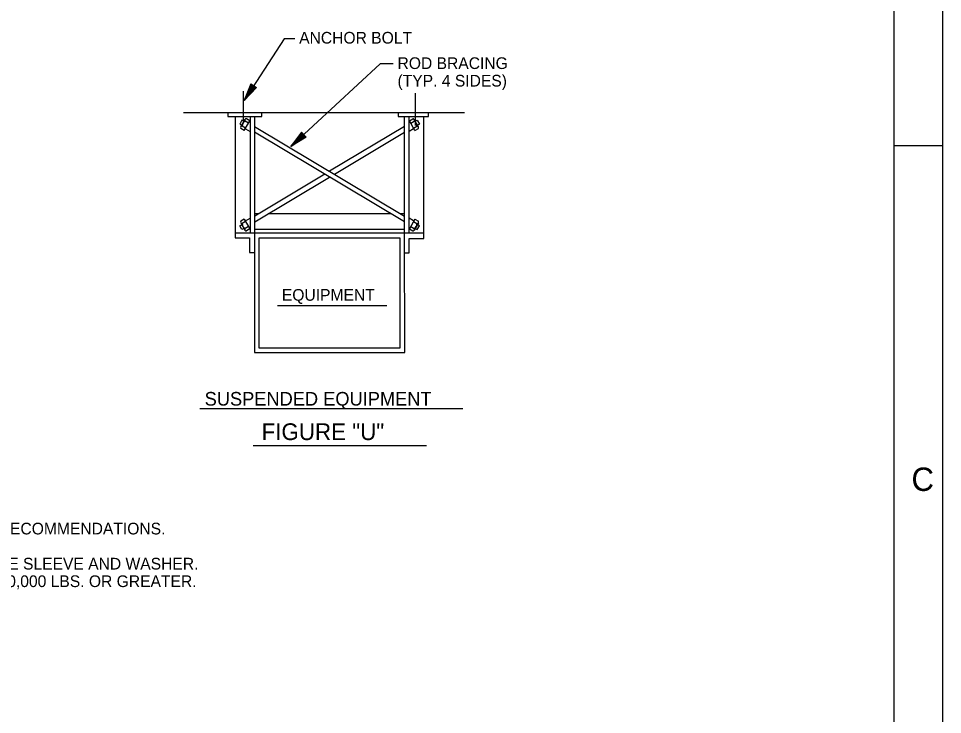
# Model space of a CAD drawing. Extents: x 9999.96 to 10005.26, y 9999.88 to 10002.38.
# Drawn here: x 10002.67 to 10003.46, y 10001.252 to 10001.847 of the extents above; entities that cross this region are included whole.
import ezdxf

# ---------------------------------------------------------------- set-up
doc = ezdxf.new("R2010")
doc.units = 0
doc.layers.add('Level 1', color=7, linetype='Continuous')
doc.layers.add('Level 2', color=7, linetype='Continuous')

msp = doc.modelspace()

# ---------------------------------------------------------------- linework, layer by layer
at = {"layer": 'Level 1'}
for p, q in [((10003.46033, 10002.38453), (10003.46033, 9999.88453)), ((10003.41867, 10002.34286), (10003.41867, 9999.9262)), ((10003.46033, 10001.7384), (10003.41898, 10001.7384))]:
    msp.add_line(p, q, dxfattribs=at)
at = {"layer": 'Level 2'}
for p, q in [((10002.86842, 10001.79143), (10002.86275, 10001.77716)), ((10002.86275, 10001.77716), (10002.86906, 10001.791)), ((10002.86275, 10001.77716), (10002.86978, 10001.79056)), ((10002.86275, 10001.77716), (10002.87033, 10001.79019)), ((10002.87093, 10001.78981), (10002.86275, 10001.77716)), ((10002.86275, 10001.77716), (10002.87155, 10001.78939)), ((10002.86275, 10001.77716), (10002.87219, 10001.78899)), ((10002.86275, 10001.77716), (10002.87279, 10001.78859)), ((10002.86842, 10001.79143), (10002.87347, 10001.78814)), ((10002.86217, 10001.75745), (10002.86217, 10001.7852)), ((10002.87347, 10001.78814), (10002.86275, 10001.77716)), ((10003.00942, 10001.75571), (10003.00942, 10001.78346)), ((10002.81084, 10001.76697), (10003.05132, 10001.76697)), ((10002.85521, 10001.76349), (10002.85521, 10001.66368)), ((10002.85989, 10001.75465), (10002.86347, 10001.76084)), ((10002.8628, 10001.75157), (10002.86757, 10001.75984)), ((10002.86639, 10001.75778), (10002.8635, 10001.75945)), ((10002.86757, 10001.75984), (10002.86471, 10001.7615)), ((10002.86782, 10001.76349), (10002.86782, 10001.66368)), ((10002.87174, 10001.76349), (10002.87174, 10001.66368)), ((10003.00002, 10001.66366), (10003.00002, 10001.76349)), ((10003.00394, 10001.66366), (10003.00394, 10001.76349)), ((10003.00418, 10001.75984), (10003.00704, 10001.7615)), ((10003.00895, 10001.75157), (10003.00418, 10001.75984)), ((10003.00536, 10001.75778), (10003.00825, 10001.75945)), ((10003.01186, 10001.75465), (10003.00828, 10001.76084)), ((10003.01655, 10001.66366), (10003.01655, 10001.76349)), ((10002.8628, 10001.75157), (10002.85992, 10001.75324)), ((10002.86398, 10001.75363), (10002.86109, 10001.75529)), ((10002.864, 10001.75281), (10002.86785, 10001.75051)), ((10002.87174, 10001.75494), (10003.00002, 10001.67831)), ((10003.00002, 10001.67332), (10002.87174, 10001.74994)), ((10002.91177, 10001.75016), (10002.90275, 10001.73773)), ((10002.90275, 10001.73773), (10002.91229, 10001.74959)), ((10002.90275, 10001.73773), (10002.91288, 10001.74899)), ((10002.91177, 10001.75016), (10002.91585, 10001.74572)), ((10003.00008, 10001.75494), (10002.93592, 10001.7166)), ((10002.94009, 10001.71411), (10003.00008, 10001.74994)), ((10003.00775, 10001.75281), (10003.0039, 10001.75051)), ((10003.00777, 10001.75363), (10003.01066, 10001.75529)), ((10003.00895, 10001.75157), (10003.01183, 10001.75324)), ((10002.90275, 10001.73773), (10002.91331, 10001.74848)), ((10002.9138, 10001.74797), (10002.90275, 10001.73773)), ((10002.90275, 10001.73773), (10002.9143, 10001.74741)), ((10002.90275, 10001.73773), (10002.91482, 10001.74686)), ((10002.90275, 10001.73773), (10002.9153, 10001.74633)), ((10002.91585, 10001.74572), (10002.90275, 10001.73773)), ((10002.93174, 10001.71411), (10002.8718, 10001.67831)), ((10002.8718, 10001.67332), (10002.93592, 10001.71161)), ((10002.87497, 10001.68021), (10002.87174, 10001.68021)), ((10002.98842, 10001.68021), (10002.88326, 10001.68021)), ((10003.00002, 10001.68021), (10002.99664, 10001.68021)), ((10002.85989, 10001.67252), (10002.86347, 10001.66632)), ((10002.8628, 10001.67559), (10002.85992, 10001.67393)), ((10002.86398, 10001.67354), (10002.86109, 10001.67188)), ((10002.8628, 10001.67559), (10002.86757, 10001.66732)), ((10002.864, 10001.67435), (10002.86785, 10001.67666)), ((10003.00775, 10001.67435), (10003.0039, 10001.67666)), ((10003.00895, 10001.67559), (10003.00418, 10001.66732)), ((10003.00777, 10001.67354), (10003.01066, 10001.67188)), ((10003.01186, 10001.67252), (10003.00828, 10001.66632)), ((10003.00895, 10001.67559), (10003.01183, 10001.67393)), ((10002.85509, 10001.66373), (10002.85509, 10001.6598)), ((10003.01655, 10001.66368), (10002.85521, 10001.66368)), ((10002.86639, 10001.66939), (10002.8635, 10001.66772)), ((10002.86757, 10001.66732), (10002.86471, 10001.66567)), ((10003.00002, 10001.66671), (10002.87174, 10001.66671)), ((10003.00418, 10001.66732), (10003.00704, 10001.66567)), ((10003.00536, 10001.66939), (10003.00825, 10001.66772)), ((10003.01653, 10001.65927), (10003.01653, 10001.66366)), ((10002.85509, 10001.6598), (10002.86736, 10001.6598)), ((10002.86736, 10001.6598), (10002.86736, 10001.64722)), ((10003.00395, 10001.64701), (10003.00395, 10001.65927)), ((10003.00395, 10001.65927), (10003.01653, 10001.65927)), ((10002.86736, 10001.64722), (10002.87174, 10001.64722)), ((10003.00002, 10001.64701), (10003.00395, 10001.64701)), ((10002.89139, 10001.60182), (10002.98479, 10001.60182)), ((10002.82493, 10001.51374), (10003.04992, 10001.51374)), ((10002.87057, 10001.48203), (10003.01883, 10001.48203))]:
    msp.add_line(p, q, dxfattribs=at)
for points in [[(10002.90623, 10001.82991), (10002.89695, 10001.82991), (10002.86275, 10001.77716)], [(10002.99028, 10001.80846), (10002.97927, 10001.80846), (10002.90275, 10001.73773)], [(10002.84869, 10001.76697), (10002.84869, 10001.76349), (10002.87783, 10001.76349), (10002.87783, 10001.76697)], [(10002.99443, 10001.76697), (10002.99443, 10001.76349), (10003.02052, 10001.76349), (10003.02052, 10001.76697)], [(10002.86264, 10001.75946), (10002.86091, 10001.76046), (10002.85895, 10001.75706), (10002.86068, 10001.75606)], [(10003.00911, 10001.75946), (10003.01084, 10001.76046), (10003.0128, 10001.75706), (10003.01107, 10001.75606)], [(10002.86264, 10001.66771), (10002.86091, 10001.66671), (10002.85895, 10001.6701), (10002.86068, 10001.6711)], [(10003.00911, 10001.66771), (10003.01084, 10001.66671), (10003.0128, 10001.6701), (10003.01107, 10001.6711)], [(10002.87174, 10001.66368), (10002.87174, 10001.56175), (10003.00015, 10001.56175), (10003.00002, 10001.66366)]]:
    msp.add_lwpolyline(points, dxfattribs=at)
msp.add_lwpolyline([(10002.87529, 10001.65933), (10002.87529, 10001.56576), (10002.99613, 10001.56576), (10002.99613, 10001.65933)], close=True, dxfattribs=at)
for centre, radius, start, end in [((10002.8655, 10001.75553), 0.00441, 117.00616, 182.94297), ((10002.86463, 10001.76016), 0.00134, 86.78269, 211.8391), ((10003.00712, 10001.76016), 0.00134, 328.1609, 93.21731), ((10003.00625, 10001.75553), 0.00441, 357.05703, 62.99384), ((10002.86104, 10001.75396), 0.00134, 87.8877, 212.03419), ((10003.01071, 10001.75396), 0.00134, 327.96581, 92.1123), ((10002.86104, 10001.6732), 0.00134, 147.96581, 272.1123), ((10002.8655, 10001.67164), 0.00441, 177.05703, 242.99384), ((10003.00625, 10001.67164), 0.00441, 297.00616, 2.94297), ((10003.01071, 10001.6732), 0.00134, 267.8877, 32.03419), ((10002.86463, 10001.667), 0.00134, 148.1609, 273.21731), ((10003.00712, 10001.667), 0.00134, 266.78269, 31.8391)]:
    msp.add_arc(centre, radius, start, end, dxfattribs=at)

# ---------------------------------------------------------------- texts
at = {"layer": 'Level 1'}
msp.add_text('C', height=0.02, dxfattribs=at).set_placement((10003.43375, 10001.44326))
at = {"layer": 'Level 2'}
for s, height, p in [('ANCHOR BOLT', 0.01, (10002.90982, 10001.82582)), ('ROD BRACING', 0.01, (10002.994, 10001.80409)), ('(TYP. 4 SIDES)', 0.01, (10002.994, 10001.78909)), ('EQUIPMENT', 0.01, (10002.89504, 10001.60591)), ('SUSPENDED EQUIPMENT', 0.0116667, (10002.82896, 10001.51623)), ('FIGURE "U"', 0.014301, (10002.87768, 10001.48676)), ('1. CLEARANCES AT SIDES FOR SPRING MOUNTED EQUIPMENT AS IN FIG. "R" & "S", SHALL BE IN ACCORDANCE WITH MFR\'S. RECOMMENDATIONS.', 0.01, (10001.83844, 10001.40605)), ('3. IF EQUIPMENT IS MOUNTED ON NEOPRENE PADS, ANCHOR BOLTS SHALL BE ISOLATED FROM EQUIPMENT BY A NEOPRENE SLEEVE AND WASHER.', 0.01, (10001.83986, 10001.37605)), ('4. PROVIDE A MINIMUM OF (4) 1/2" ANCHOR BOLTS FOR EQUIPMENT UP TO 10,000 LBS. AND (4) 3/4" BOLTS FOR EQUIPMENT 10,000 LBS. OR GREATER.', 0.01, (10001.83986, 10001.36105))]:
    msp.add_text(s, height=height, dxfattribs=at).set_placement(p)

doc.saveas('drawing.dxf')
